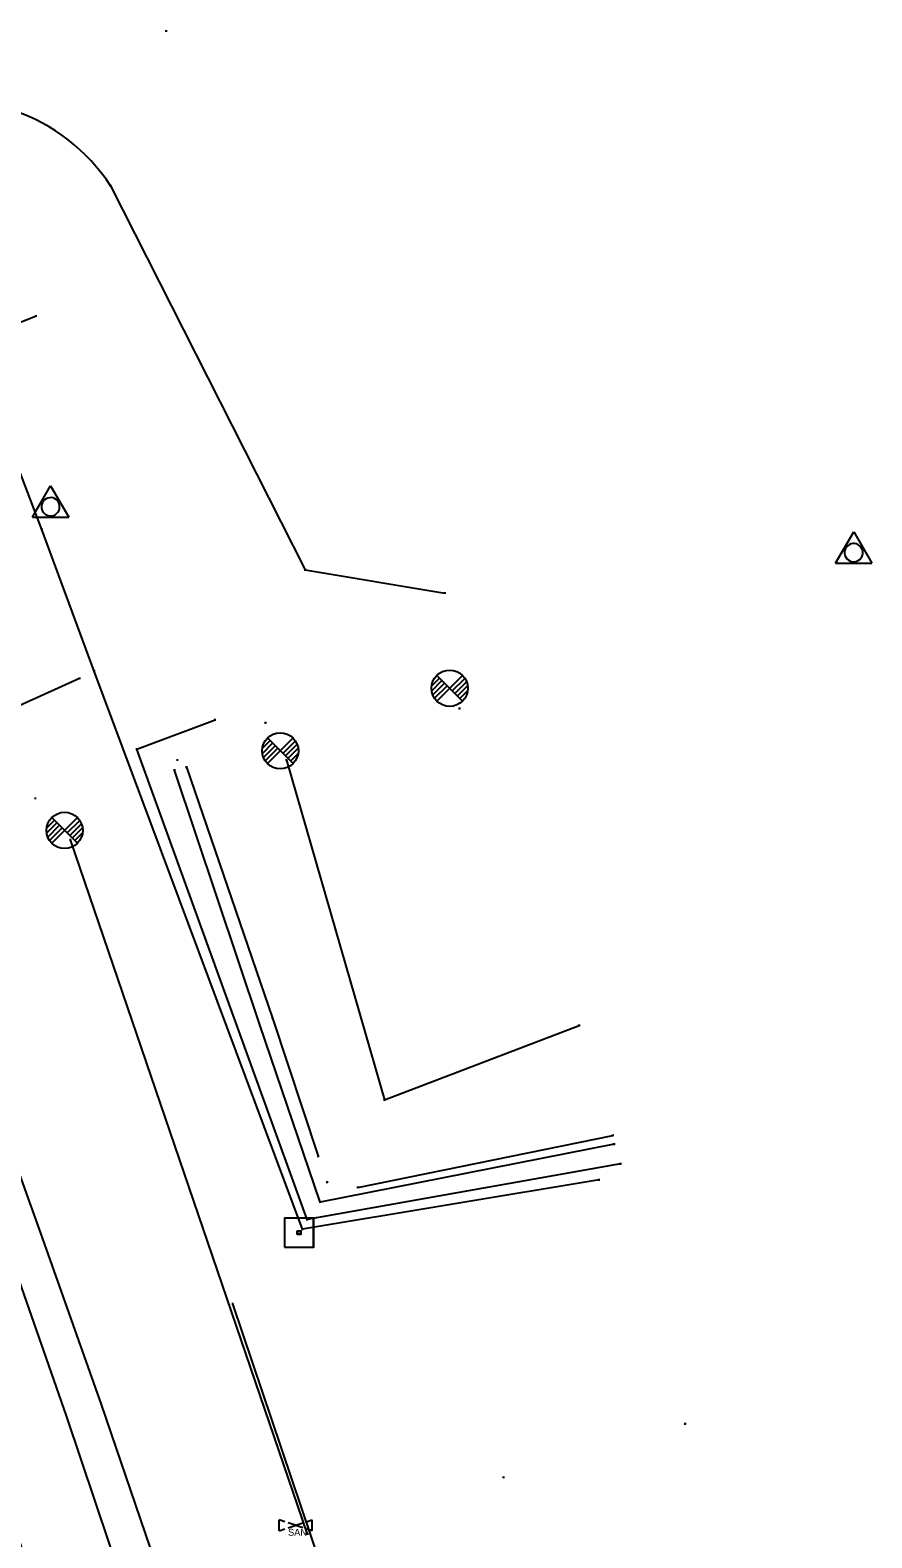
# Model space of a CAD drawing. Extents: x 1954856 to 2011933, y 399149 to 426294.
# Drawn here: x 2005022.3 to 2005138.3, y 407789.5 to 407997.5 of the extents above; entities that cross this region are included whole.
import ezdxf

# ---------------------------------------------------------------- set-up
doc = ezdxf.new("R2010")
doc.units = 0
for name, color, linetype in [('BankMent_ep', 7, 'Continuous'), ('BaselineSurvey', 7, 'Continuous'), ('Driveway_ep', 7, 'Continuous'), ('Fence_ep', 7, 'Continuous'), ('Gates_ep', 7, 'Continuous'), ('MonumentCC_ep', 7, 'Continuous'), ('MonumentIRC_ep', 7, 'Continuous'), ('PavtAsphalt_ep', 7, 'Continuous'), ('PointLocator_ep', 7, 'Continuous'), ('ShldrPaved_ep', 7, 'Continuous'), ('SignMulti_ep', 7, 'Continuous'), ('TreeLineScatter_ep', 7, 'Continuous'), ('ValveSewer_ep', 7, 'Continuous'), ('XSPt_ep', 7, 'Continuous')]:
    doc.layers.add(name, color=color, linetype=linetype)

msp = doc.modelspace()

# ---------------------------------------------------------------- linework, layer by layer
at = {"layer": 'BankMent_ep'}
for p, q in [((2005036.96, 407898.31), (2005047.75, 407902.38)), ((2005043.81, 407895.84), (2005055.67, 407861.24)), ((2005057.6, 407896.83), (2005071.14, 407849.94)), ((2005055.67, 407861.24), (2005061.98, 407842.18)), ((2005071.14, 407849.94), (2005097.97, 407860.22)), ((2005067.46, 407837.88), (2005102.61, 407845.05))]:
    msp.add_line(p, q, dxfattribs=at)
for points in [[(2005103.68, 407841.11), (2005060.47, 407833.43), (2005036.96, 407898.31)], [(2005102.8, 407843.82), (2005062.25, 407835.86), (2005053.92, 407860.3), (2005042.17, 407895.44)], [(2005060.5, 407790.06), (2005027.81, 407885.82)]]:
    msp.add_lwpolyline(points, dxfattribs=at)
at = {"layer": 'BaselineSurvey'}
msp.add_arc((2002584.46, 406985.33), 2565.51, 11.93882, 21.72713, dxfattribs=at)
msp.add_arc((2002584.46, 406985.33), 2565.51, 11.93882, 21.72713, dxfattribs=at)
at = {"layer": 'Driveway_ep'}
for p, q in [((2005033.36, 407976.05), (2005060.19, 407923.07)), ((2005060.19, 407923.07), (2005079.44, 407919.87))]:
    msp.add_line(p, q, dxfattribs=at)
msp.add_lwpolyline([(2005029.08, 407908.1), (2005003.65, 407896.57)], dxfattribs=at)
msp.add_arc((2005011.47, 407961.66), 26.19, 33.3196, 108.2016, dxfattribs=at)
at = {"layer": 'Fence_ep'}
for points in [[(2005023.87, 407928.64), (2005005.71, 407976.23)], [(2005100.71, 407838.9), (2005059.83, 407832.11), (2005031.07, 407909.11)]]:
    msp.add_lwpolyline(points, dxfattribs=at)
at = {"layer": 'Gates_ep'}
msp.add_lwpolyline([(2005031.07, 407909.11), (2005023.87, 407928.64)], dxfattribs=at)
at = {"layer": 'MonumentCC_ep'}
for p, q in [((2005059.34, 407831.61), (2005059.34, 407831.61)), ((2005059.35, 407831.64), (2005059.35, 407831.64))]:
    msp.add_line(p, q, dxfattribs=at)
for points in [[(2005057.34, 407829.61), (2005061.34, 407829.61), (2005061.34, 407833.61), (2005057.34, 407833.61), (2005057.34, 407829.61)], [(2005057.35, 407829.64), (2005061.36, 407829.64), (2005061.36, 407833.64), (2005057.35, 407833.64), (2005057.35, 407829.64)]]:
    msp.add_lwpolyline(points, dxfattribs=at)
for points in [[(2005059.1, 407831.37), (2005059.1, 407831.85), (2005059.57, 407831.85), (2005059.57, 407831.37)], [(2005059.12, 407831.41), (2005059.12, 407831.88), (2005059.59, 407831.88), (2005059.59, 407831.41)]]:
    msp.add_lwpolyline(points, close=True, dxfattribs=at)
at = {"layer": 'MonumentIRC_ep'}
for p, q in [((2005022.57, 407930.33), (2005025.07, 407934.66)), ((2005025.07, 407934.66), (2005027.57, 407930.33)), ((2005022.57, 407930.33), (2005027.57, 407930.33)), ((2005025.07, 407931.77), (2005025.07, 407931.77)), ((2005133.33, 407923.99), (2005135.83, 407928.32)), ((2005135.83, 407928.32), (2005138.33, 407923.99)), ((2005133.33, 407923.99), (2005138.33, 407923.99)), ((2005135.83, 407925.44), (2005135.83, 407925.44))]:
    msp.add_line(p, q, dxfattribs=at)
for centre in [(2005025.07, 407931.77), (2005135.83, 407925.44)]:
    msp.add_arc(centre, 1.26, 209.9294, 209.03, dxfattribs=at)
at = {"layer": 'PavtAsphalt_ep'}
msp.add_lwpolyline([(2005064.38, 407686.9), (2005057.48, 407710.97), (2005050.32, 407734.96), (2005042.9, 407758.87), (2005035.21, 407782.69), (2005027.26, 407806.35), (2005019.06, 407829.93), (2005010.67, 407853.44), (2005002.12, 407876.9), (2004994.47, 407897.59), (2004986.75, 407918.26), (2004978.98, 407938.91)], dxfattribs=at)
at = {"layer": 'PointLocator_ep'}
for p, q in [((2005041.15, 407997.39), (2005040.9, 407997.39)), ((2005041.02, 407997.27), (2005041.02, 407997.52)), ((2005041.02, 407997.39), (2005041.02, 407997.39)), ((2005033.48, 407976.05), (2005033.23, 407976.05)), ((2005033.36, 407975.93), (2005033.36, 407976.18)), ((2005033.36, 407976.05), (2005033.36, 407976.05)), ((2005023.2, 407958.08), (2005022.95, 407958.08)), ((2005023.07, 407957.95), (2005023.07, 407958.2)), ((2005023.07, 407958.08), (2005023.07, 407958.08)), ((2005024, 407928.64), (2005023.75, 407928.64)), ((2005023.87, 407928.51), (2005023.87, 407928.76)), ((2005023.87, 407928.64), (2005023.87, 407928.64)), ((2005060.32, 407923.07), (2005060.07, 407923.07)), ((2005060.19, 407922.95), (2005060.19, 407923.2)), ((2005060.19, 407923.07), (2005060.19, 407923.07)), ((2005079.56, 407919.87), (2005079.31, 407919.87)), ((2005079.44, 407919.74), (2005079.44, 407919.99)), ((2005079.44, 407919.87), (2005079.44, 407919.87)), ((2005029.21, 407908.1), (2005028.96, 407908.1)), ((2005029.08, 407907.98), (2005029.08, 407908.23)), ((2005029.08, 407908.1), (2005029.08, 407908.1)), ((2005031.2, 407909.11), (2005030.95, 407909.11)), ((2005031.07, 407908.99), (2005031.07, 407909.24)), ((2005031.07, 407909.11), (2005031.07, 407909.11)), ((2005081.6, 407903.93), (2005081.35, 407903.93)), ((2005081.47, 407903.8), (2005081.47, 407904.05)), ((2005081.47, 407903.93), (2005081.47, 407903.93)), ((2005047.87, 407902.38), (2005047.62, 407902.38)), ((2005047.75, 407902.26), (2005047.75, 407902.51)), ((2005047.75, 407902.38), (2005047.75, 407902.38)), ((2005054.85, 407901.96), (2005054.6, 407901.96)), ((2005054.72, 407901.83), (2005054.72, 407902.08)), ((2005054.72, 407901.96), (2005054.72, 407901.96)), ((2005037.09, 407898.31), (2005036.84, 407898.31)), ((2005036.96, 407898.19), (2005036.96, 407898.44)), ((2005036.96, 407898.31), (2005036.96, 407898.31)), ((2005042.56, 407896.7), (2005042.56, 407896.95)), ((2005057.6, 407896.71), (2005057.6, 407896.96)), ((2005042.29, 407895.44), (2005042.04, 407895.44)), ((2005042.17, 407895.32), (2005042.17, 407895.57)), ((2005042.17, 407895.44), (2005042.17, 407895.44)), ((2005042.68, 407896.83), (2005042.43, 407896.83)), ((2005042.56, 407896.83), (2005042.56, 407896.83)), ((2005043.94, 407895.84), (2005043.69, 407895.84)), ((2005043.81, 407895.71), (2005043.81, 407895.96)), ((2005043.81, 407895.84), (2005043.81, 407895.84)), ((2005057.72, 407896.83), (2005057.47, 407896.83)), ((2005057.6, 407896.83), (2005057.6, 407896.83)), ((2005023.1, 407891.54), (2005022.85, 407891.54)), ((2005022.98, 407891.42), (2005022.98, 407891.67)), ((2005022.98, 407891.54), (2005022.98, 407891.54)), ((2005027.93, 407885.82), (2005027.68, 407885.82)), ((2005027.81, 407885.7), (2005027.81, 407885.95)), ((2005027.81, 407885.82), (2005027.81, 407885.82)), ((2005054.04, 407860.3), (2005053.79, 407860.3)), ((2005053.92, 407860.18), (2005053.92, 407860.43)), ((2005053.92, 407860.3), (2005053.92, 407860.3)), ((2005055.79, 407861.24), (2005055.54, 407861.24)), ((2005055.67, 407861.11), (2005055.67, 407861.36)), ((2005055.67, 407861.24), (2005055.67, 407861.24)), ((2005098.09, 407860.22), (2005097.84, 407860.22)), ((2005097.97, 407860.09), (2005097.97, 407860.34)), ((2005097.97, 407860.22), (2005097.97, 407860.22)), ((2005071.26, 407849.94), (2005071.01, 407849.94)), ((2005071.14, 407849.82), (2005071.14, 407850.07)), ((2005071.14, 407849.94), (2005071.14, 407849.94)), ((2005102.74, 407845.05), (2005102.49, 407845.05)), ((2005102.61, 407844.92), (2005102.61, 407845.17)), ((2005102.61, 407845.05), (2005102.61, 407845.05)), ((2005102.92, 407843.82), (2005102.67, 407843.82)), ((2005102.8, 407843.69), (2005102.8, 407843.94)), ((2005102.8, 407843.82), (2005102.8, 407843.82)), ((2005062.1, 407842.18), (2005061.85, 407842.18)), ((2005061.98, 407842.05), (2005061.98, 407842.3)), ((2005061.98, 407842.18), (2005061.98, 407842.18)), ((2005103.8, 407841.11), (2005103.55, 407841.11)), ((2005103.68, 407840.99), (2005103.68, 407841.24)), ((2005103.68, 407841.11), (2005103.68, 407841.11)), ((2005063.21, 407838.45), (2005063.21, 407838.7)), ((2005100.84, 407838.9), (2005100.59, 407838.9)), ((2005100.71, 407838.78), (2005100.71, 407839.03)), ((2005100.71, 407838.9), (2005100.71, 407838.9)), ((2005063.34, 407838.58), (2005063.09, 407838.58)), ((2005063.21, 407838.58), (2005063.21, 407838.58)), ((2005067.58, 407837.88), (2005067.33, 407837.88)), ((2005067.46, 407837.75), (2005067.46, 407838)), ((2005067.46, 407837.88), (2005067.46, 407837.88)), ((2005062.38, 407835.86), (2005062.13, 407835.86)), ((2005062.25, 407835.74), (2005062.25, 407835.99)), ((2005062.25, 407835.86), (2005062.25, 407835.86)), ((2005060.59, 407833.43), (2005060.34, 407833.43)), ((2005060.47, 407833.3), (2005060.47, 407833.55)), ((2005060.47, 407833.43), (2005060.47, 407833.43)), ((2005059.95, 407832.11), (2005059.7, 407832.11)), ((2005059.83, 407831.99), (2005059.83, 407832.24)), ((2005059.83, 407832.11), (2005059.83, 407832.11)), ((2005050.31, 407821.81), (2005050.06, 407821.81)), ((2005050.19, 407821.69), (2005050.19, 407821.94)), ((2005050.19, 407821.81), (2005050.19, 407821.81)), ((2005112.58, 407805.12), (2005112.58, 407805.37)), ((2005112.71, 407805.25), (2005112.46, 407805.25)), ((2005112.58, 407805.25), (2005112.58, 407805.25)), ((2005087.68, 407797.87), (2005087.43, 407797.87)), ((2005087.55, 407797.75), (2005087.55, 407798)), ((2005087.55, 407797.87), (2005087.55, 407797.87)), ((2005060.62, 407790.06), (2005060.37, 407790.06)), ((2005060.5, 407789.94), (2005060.5, 407790.19)), ((2005060.5, 407790.06), (2005060.5, 407790.06))]:
    msp.add_line(p, q, dxfattribs=at)
at = {"layer": 'ShldrPaved_ep'}
msp.add_lwpolyline([(2005069.77, 407687.36), (2005062.79, 407711.7), (2005055.56, 407735.97), (2005048.04, 407760.13), (2005040.2, 407784.19), (2005032.08, 407807.92), (2005023.72, 407831.57), (2005015.21, 407855.18), (2005006.69, 407878.78), (2004999.23, 407899.49), (2004991.68, 407920.16), (2004983.86, 407940.74)], dxfattribs=at)
at = {"layer": 'SignMulti_ep'}
msp.add_lwpolyline([(2005023.07, 407958.08), (2005014.74, 407954.71)], dxfattribs=at)
at = {"layer": 'TreeLineScatter_ep'}
msp.add_lwpolyline([(2005090.8, 407701.38), (2005050.19, 407821.81)], dxfattribs=at)
at = {"layer": 'ValveSewer_ep'}
for p, q in [((2005057.36, 407791.76), (2005056.61, 407792.01)), ((2005056.61, 407790.51), (2005056.61, 407792.01)), ((2005059.86, 407790.93), (2005057.86, 407791.6)), ((2005057.86, 407790.93), (2005059.86, 407791.6)), ((2005058.86, 407791.26), (2005058.86, 407791.26)), ((2005060.36, 407791.76), (2005061.11, 407792.01)), ((2005061.11, 407792.01), (2005061.11, 407790.51)), ((2005056.61, 407790.51), (2005057.36, 407790.76)), ((2005061.11, 407790.51), (2005060.36, 407790.76))]:
    msp.add_line(p, q, dxfattribs=at)
at = {"layer": 'XSPt_ep'}
for p, q in [((2005077.63, 407907.08), (2005078.69, 407908.14)), ((2005077.63, 407906.37), (2005079.05, 407907.79)), ((2005077.78, 407905.81), (2005079.4, 407907.43)), ((2005078.34, 407904.96), (2005081.88, 407908.49)), ((2005081.88, 407904.96), (2005078.34, 407908.49)), ((2005080.46, 407906.37), (2005082.19, 407908.1)), ((2005080.82, 407906.02), (2005082.44, 407907.64)), ((2005078.02, 407905.35), (2005079.75, 407907.08)), ((2005080.11, 407906.73), (2005080.11, 407906.73)), ((2005081.17, 407905.67), (2005082.58, 407907.08)), ((2005081.52, 407905.31), (2005082.58, 407906.37)), ((2005054.28, 407898.46), (2005055.34, 407899.52)), ((2005054.28, 407897.75), (2005055.69, 407899.16)), ((2005054.98, 407896.33), (2005058.52, 407899.87)), ((2005058.52, 407896.33), (2005054.98, 407899.87)), ((2005057.1, 407897.75), (2005058.84, 407899.48)), ((2005057.46, 407897.39), (2005059.08, 407899.02)), ((2005054.42, 407897.19), (2005056.04, 407898.81)), ((2005054.66, 407896.72), (2005056.4, 407898.46)), ((2005056.75, 407898.1), (2005056.75, 407898.1)), ((2005057.81, 407897.04), (2005059.22, 407898.46)), ((2005058.16, 407896.69), (2005059.22, 407897.75)), ((2005025.24, 407885.36), (2005028.78, 407888.89)), ((2005028.78, 407885.36), (2005025.24, 407888.89)), ((2005024.54, 407887.48), (2005025.6, 407888.54)), ((2005024.54, 407886.77), (2005025.95, 407888.18)), ((2005024.68, 407886.21), (2005026.3, 407887.83)), ((2005024.93, 407885.74), (2005026.66, 407887.48)), ((2005027.01, 407887.12), (2005027.01, 407887.12)), ((2005027.37, 407886.77), (2005029.1, 407888.5)), ((2005027.72, 407886.42), (2005029.34, 407888.04)), ((2005028.07, 407886.06), (2005029.49, 407887.48)), ((2005028.43, 407885.71), (2005029.49, 407886.77))]:
    msp.add_line(p, q, dxfattribs=at)
for centre in [(2005080.11, 407906.73), (2005056.75, 407898.1), (2005027.01, 407887.12)]:
    msp.add_circle(centre, 2.5, dxfattribs=at)

# ---------------------------------------------------------------- texts
at = {"layer": 'ValveSewer_ep'}
msp.add_text('SAN', height=0.95, dxfattribs=at).set_placement((2005057.82, 407789.82))

doc.saveas('drawing.dxf')
